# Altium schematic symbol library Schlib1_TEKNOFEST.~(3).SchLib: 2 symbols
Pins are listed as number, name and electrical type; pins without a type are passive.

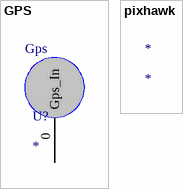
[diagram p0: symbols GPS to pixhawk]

## GPS
designator U?
pins: 0 Gps_In

## pixhawk
designator *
